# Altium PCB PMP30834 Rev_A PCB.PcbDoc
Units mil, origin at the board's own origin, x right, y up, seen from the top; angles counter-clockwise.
Board outline 2200 x 1400 mil, 4 copper layers (Top Layer, Signal Layer 1, Signal Layer 2, Bottom Layer), stack 61.668 mil thick; 56 components, 16 nets, 91 pads, 36 vias.
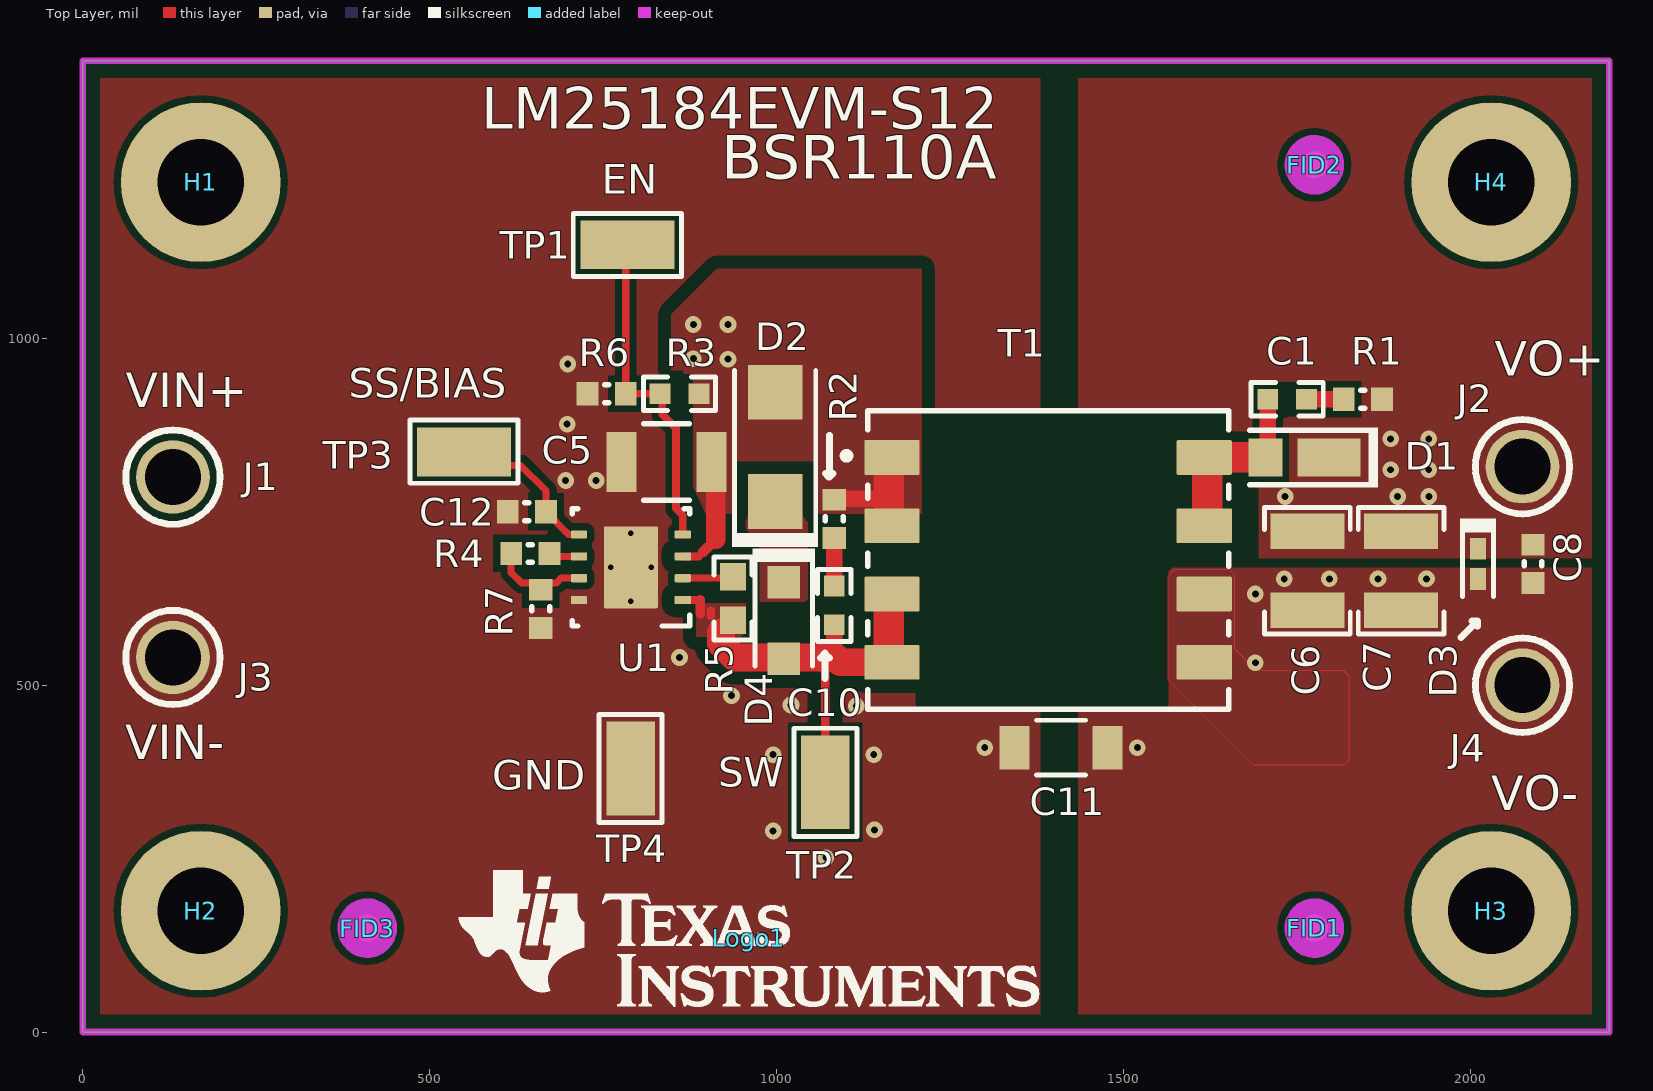
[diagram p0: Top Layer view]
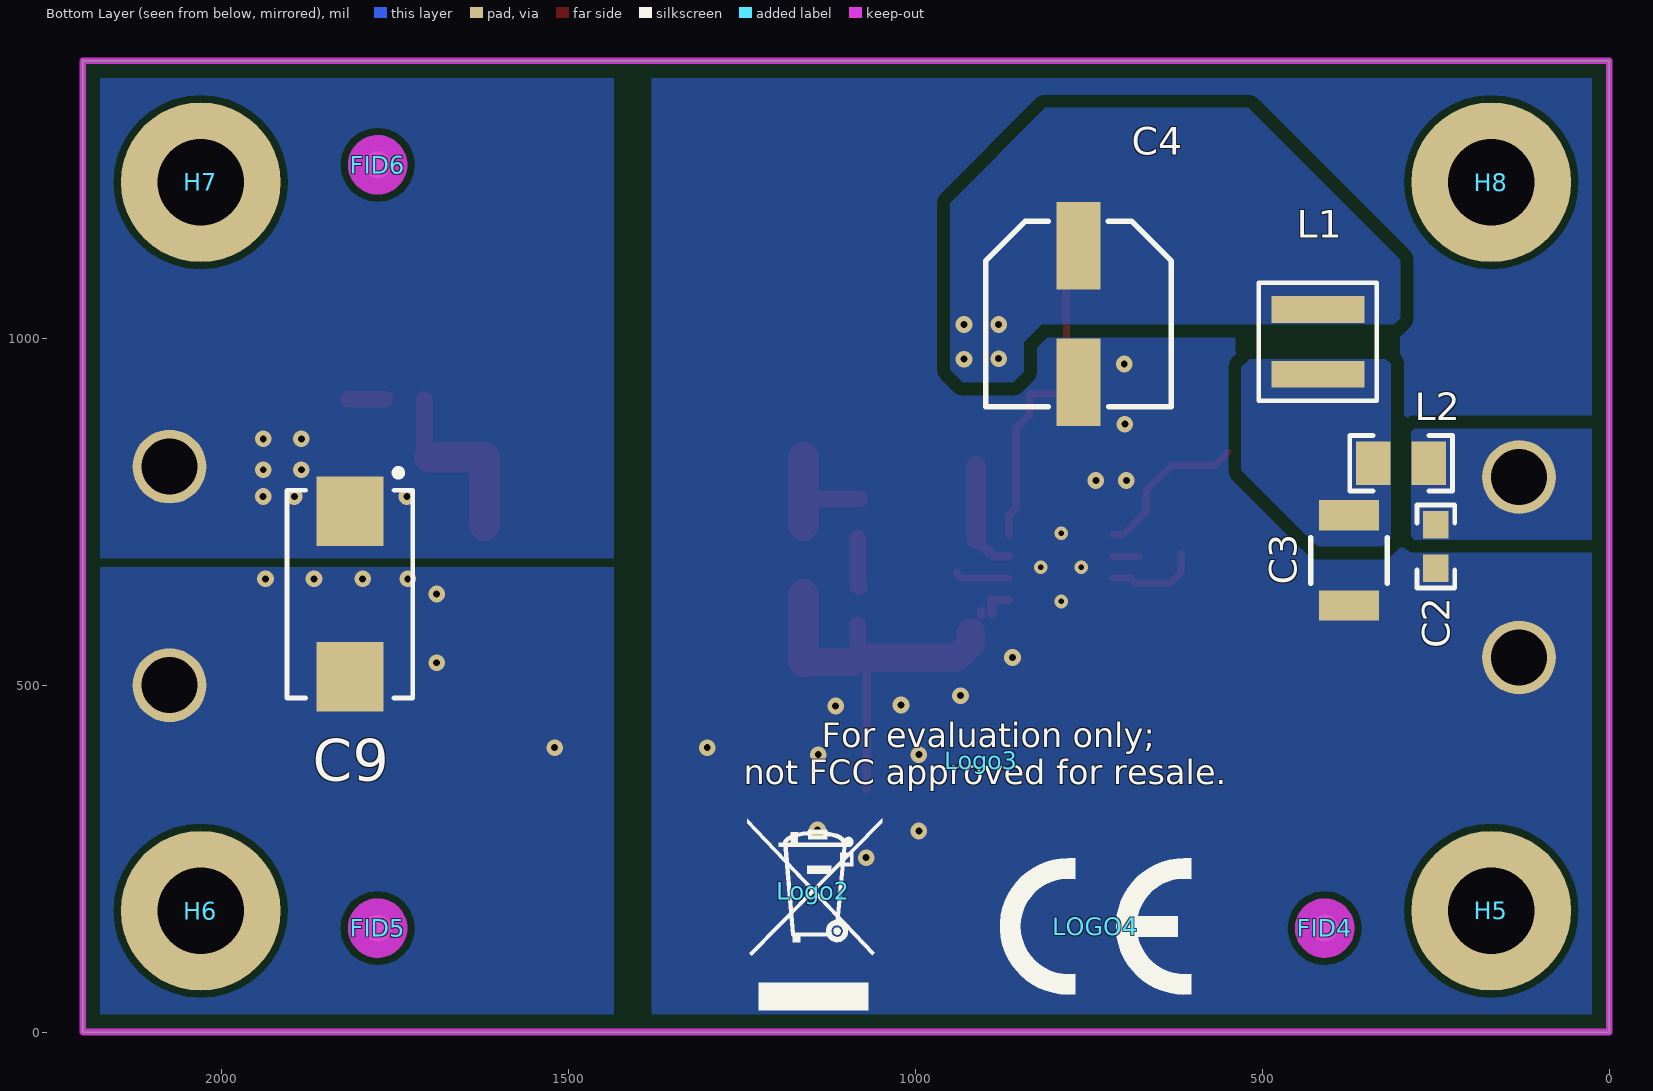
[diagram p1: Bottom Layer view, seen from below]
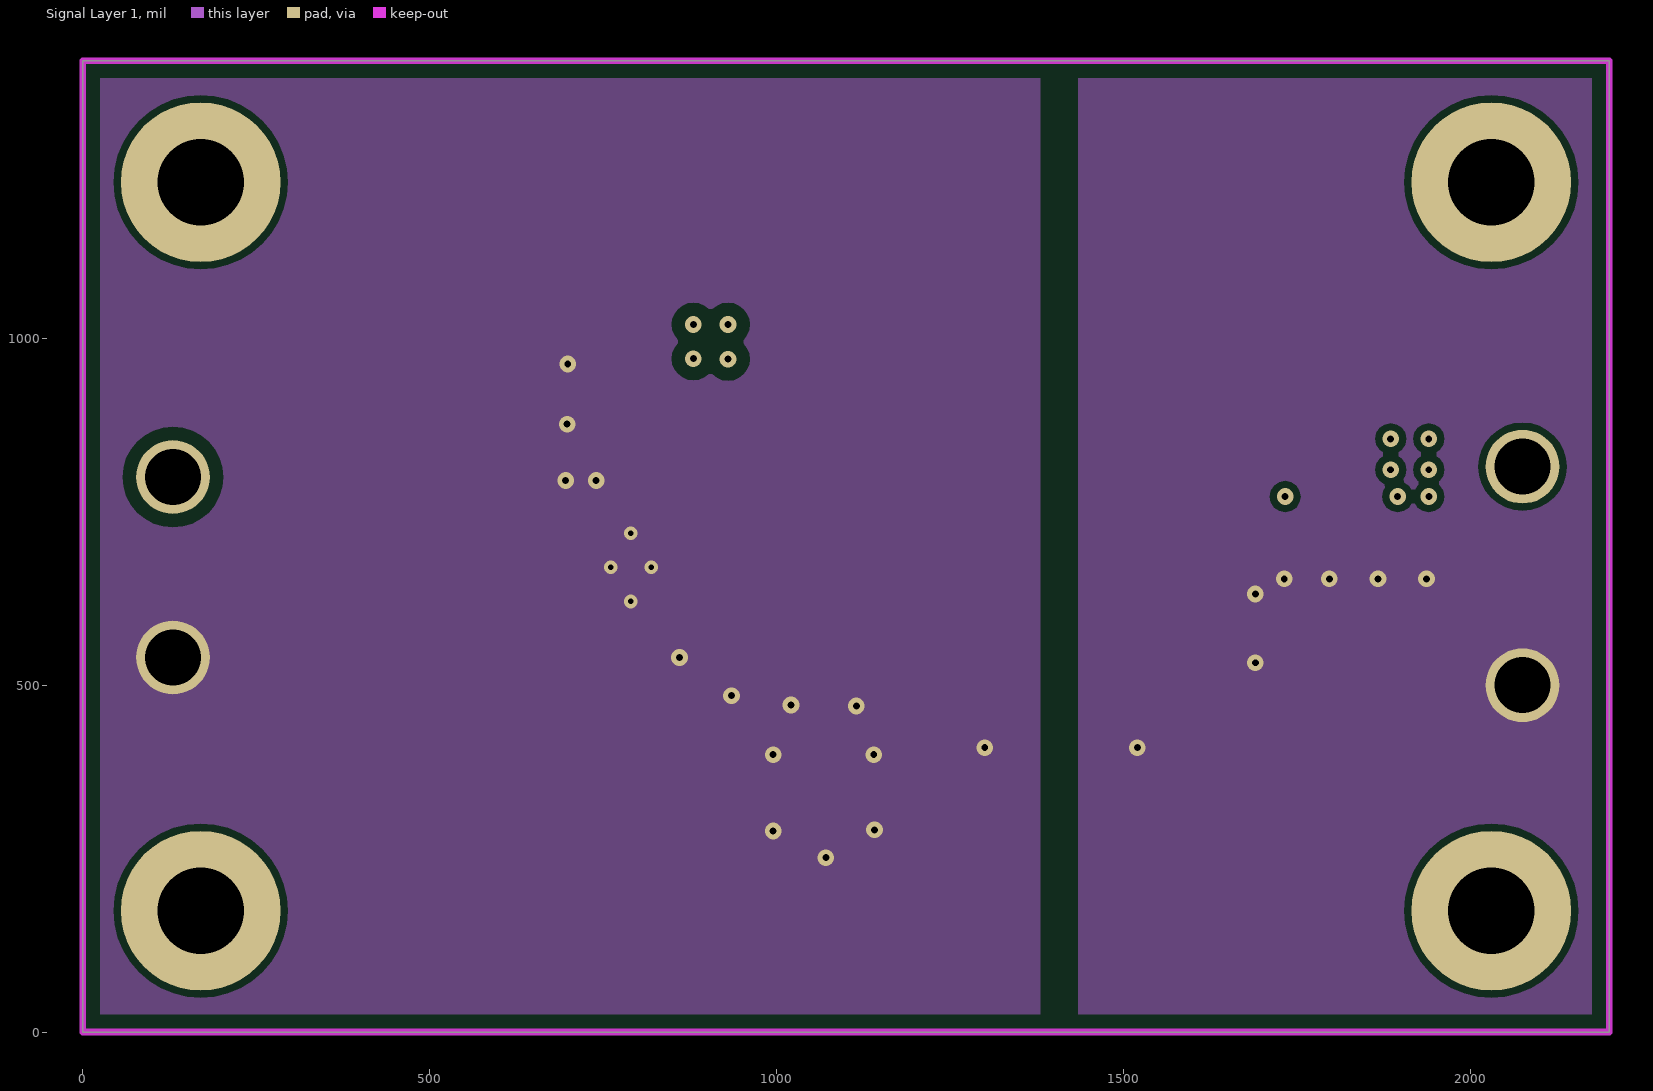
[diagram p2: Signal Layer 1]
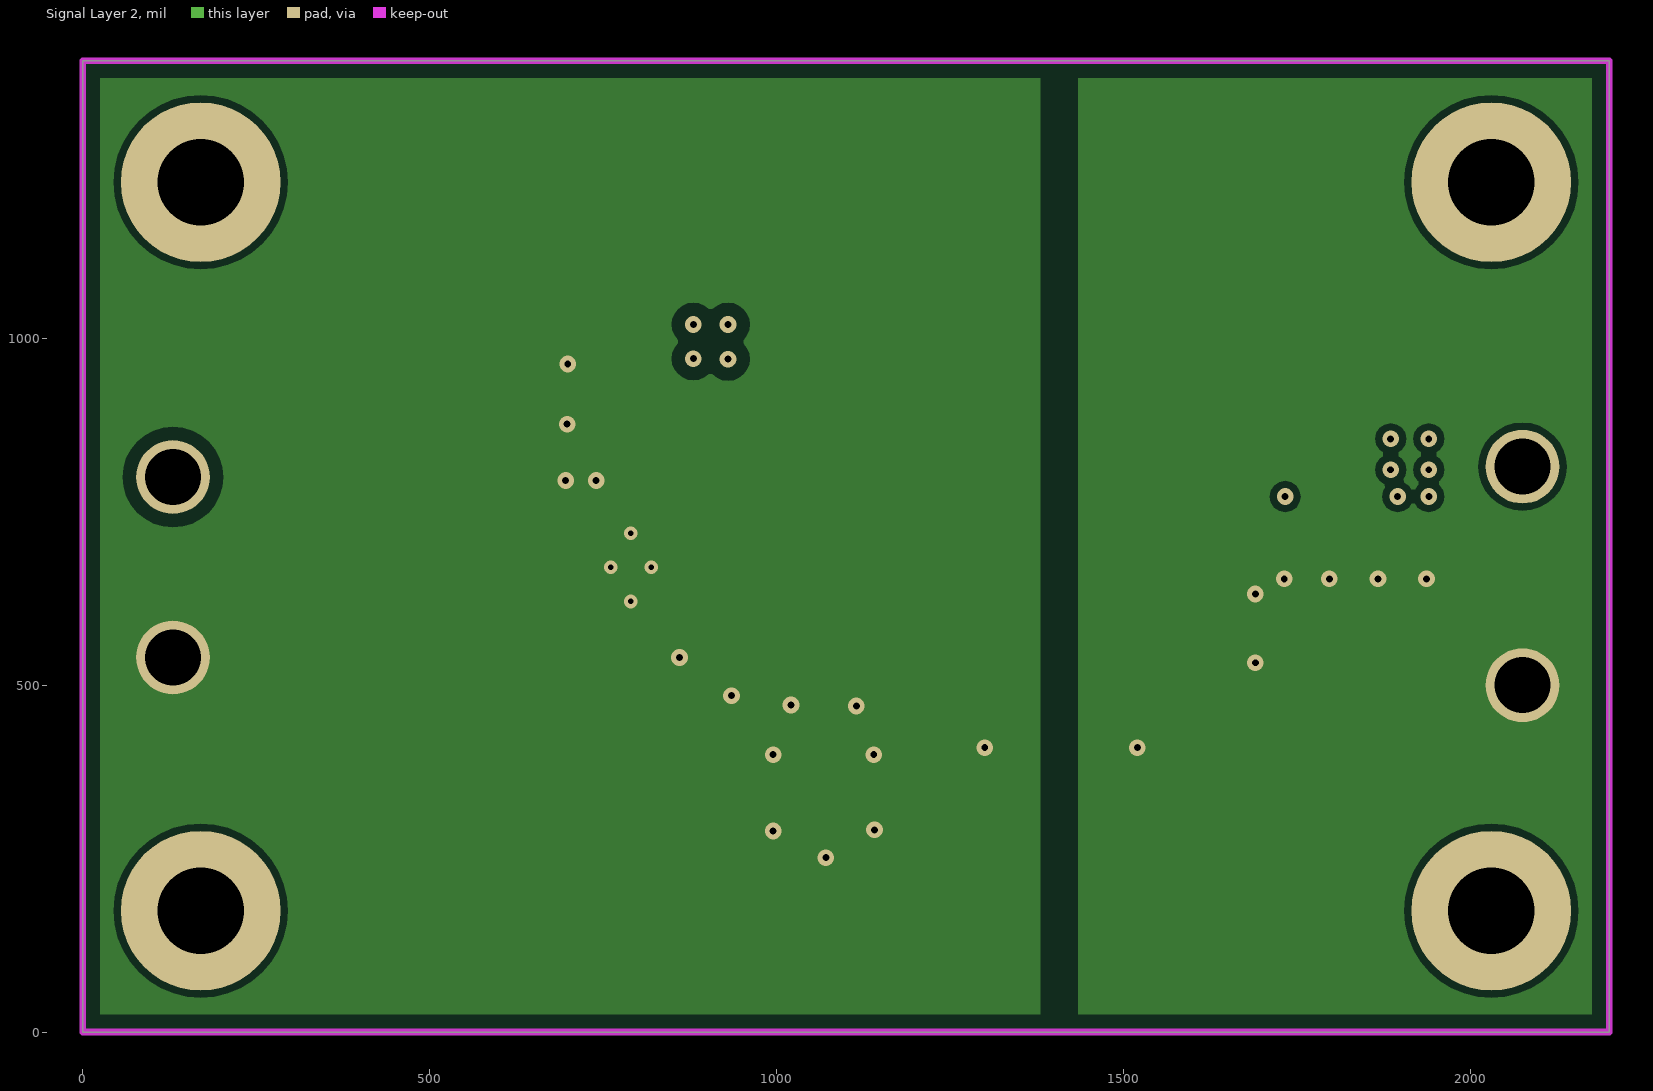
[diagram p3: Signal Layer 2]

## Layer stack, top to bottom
Top Solder: solder mask 0.4, Solder Resist, Dk 3.5
Top Layer: signal copper 1.417
Dielectric1: prepreg 6, FR-4 High Tg, Dk 4.2
Signal Layer 1: signal copper 1.417
Dielectric 2: core 44, FR-4 High Tg, Dk 4.2
Signal Layer 2: signal copper 1.417
Dielectric 3: dielectric 6, FR-4 High Tg, Dk 4.2
Bottom Layer: signal copper 1.417
Bottom Solder: solder mask 0.4, Solder Resist, Dk 3.5

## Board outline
0,0 0,1400 2200,1400 2200,0

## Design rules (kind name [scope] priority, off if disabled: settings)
AcuteAngle [All] p1: minimum=4.50000000000000E+0001 checktracksonly=FALSE
AssemblyTestPointUsage [All] p1: valid=2
BoardOutlineClearance BoardOutlineClearance_MountingHoles [OnCopper and InComponentClass('Mounting Holes')] p1: gap=40 ignorepadtopadclearanceinfootprint=FALSE
BoardOutlineClearance BoardOutlineClearance_Poly [OnCopper and IsPoly] p2: gap=25 ignorepadtopadclearanceinfootprint=FALSE
BoardOutlineClearance [OnCopper and Not InComponentClass('Logo') and not InComponentClass('FiducialMark') and not InRegion(1000,500,4000,800) and not InPoly] p3: gap=50 ignorepadtopadclearanceinfootprint=FALSE
Clearance Clearance_HV_Nets [InNetClass('HV_Nets')] p1: gap=19 ignorepadtopadclearanceinfootprint=FALSE
Clearance Clearance_Keepouts [((IsTrack Or IsArc) And Not InPoly) And IsFree and IsKeepOut vs ((IsTrack Or IsArc) And Not InPoly) And IsFree and IsKeepOut] p2: gap=0 ignorepadtopadclearanceinfootprint=FALSE
Clearance Clearance_Poly [InPolygon] p3: gap=10 ignorepadtopadclearanceinfootprint=FALSE
Clearance Clearance_FiducialMark [IsKeepOut and InComponentClass('FiducialMark') vs IsPad and InComponentClass('FiducialMark')] p4: gap=0 ignorepadtopadclearanceinfootprint=FALSE
Clearance [All] p5: gap=7.87 ignorepadtopadclearanceinfootprint=FALSE except(0: Arc-Hole Track-Hole SMDPad-Hole THPad-Hole Via-Hole Fill-Hole Poly-Hole Region-Hole Text-Hole)
ComponentClearance ComponentClearance_MountingHoles_FiducialMarks [InComponentClass('Mounting Holes') vs InComponentClass('FiducialMark')] p1: gap=50 collisioncheckmode=3 verticalgap=10 showdistances=FALSE
ComponentClearance ComponentClearance_Shunt [InComponentClass('Header') vs InComponentClass('Shunt')] p2: gap=0 collisioncheckmode=3 verticalgap=0 showdistances=FALSE
ComponentClearance ComponentClearance_Logo [InComponentClass('Logo')] p3: gap=50 collisioncheckmode=3 verticalgap=10 showdistances=FALSE
ComponentClearance ComponentClearance_ScrewToNut [(HasFootprint('NY PMS 440 0025 PH')) vs (HasFootprint('Keystone_1902C'))] p4: gap=5 collisioncheckmode=3 verticalgap=10 showdistances=FALSE
ComponentClearance ComponentClearance_MountingHoles [InComponentClass('Mounting Holes')] p5: gap=0 collisioncheckmode=3 verticalgap=0 showdistances=FALSE
ComponentClearance ComponentClearance_SmallPassives [HasFootprint('0201*') or HasFootprint('0402*') or HasFootprint('0508') or HasFootprint('0603*') or HasFootprint('0612') or HasFootprint('0805*') or HasFootprint('0815*') or HasFootprint('0830*') or HasFootprint('1206*') or HasFootprint('1210*') or HasFootprint('1808*') or HasFootprint('1812*') or HasFootprint('1825*') or HasFootprint('2010*') or HasFootprint('2220*') or HasFootprint('2225*') or HasFootprint('2512*') or HasFootprint('2728*') or HasFootprint('3518*') vs HasFootprint('0201*') or HasFootprint('0402*') or HasFootprint('0508') or HasFootprint('0603*') or HasFootprint('0612') or HasFootprint('0805*') or HasFootprint('0815*') or HasFootprint('0830*') or HasFootprint('1206*') or HasFootprint('1210*') or HasFootprint('1808*') or HasFootprint('1812*') or HasFootprint('1825*') or HasFootprint('2010*') or HasFootprint('2220*') or HasFootprint('2225*') or HasFootprint('2512*') or HasFootprint('2728*') or HasFootprint('3518*')] p6: gap=14.96 collisioncheckmode=3 verticalgap=10 showdistances=FALSE
ComponentClearance ComponentClearance_THtoSMT [IsThruComponent vs IsSMTComponent] p7: gap=20 collisioncheckmode=3 verticalgap=30 showdistances=FALSE
ComponentClearance ComponentClearance_THtoTH [IsThruComponent vs IsThruComponent] p8: gap=30 collisioncheckmode=3 verticalgap=30 showdistances=FALSE
ComponentClearance [All] p9: gap=10 collisioncheckmode=3 verticalgap=10 showdistances=FALSE
DiffPairsRouting [All] p1: maxlimit=100 minlimit=10 mostfreqgap=10 toplayer_minwidth=15 toplayer_maxwidth=15 toplayer_prefwidth=15 midlayer1_minwidth=15 midlayer1_maxwidth=15 midlayer1_prefwidth=15 midlayer2_minwidth=15 midlayer2_maxwidth=15 midlayer2_prefwidth=15 bottomlayer_minwidth=15 bottomlayer_maxwidth=15 bottomlayer_prefwidth=15 maxuncoupledlength=1000
FabricationTestPointUsage TestPointUsage [All] p1: valid=2 allowmultiple=FALSE
FabricationTestpoint Testpoint [All] p1: side=3 testpointundercomponent=TRUE minsize=40 maxsize=100 preferedsize=60 minholesize=0 maxholesize=40 preferedholesize=32 testpointgrid=1 allowsidetop=TRUE allowsidebottom=TRUE usegrid=TRUE gridtolerance=0.01
FanoutControl Fanout_LCC [IsLCC] p1: bgadir=Out bgaviamode=Centered fanoutstyle=Auto fanoutdirection=Alternating viagrid=1 // Fanout_LCC (Default Rule)
FanoutControl Fanout_BGA [IsBGA] p2: bgadir=Out bgaviamode=Centered fanoutstyle=Auto fanoutdirection=Alternating viagrid=1 // Fanout_BGA (Default Rule)
FanoutControl Fanout_Default [All] p4: bgadir=Out bgaviamode=Centered fanoutstyle=Auto fanoutdirection=Alternating viagrid=1 // Fanout_Default (Default Rule)
FanoutControl Fanout_Small [(CompPinCount < 5)] p5: bgadir=Out bgaviamode=Centered fanoutstyle=Auto fanoutdirection=OutThenIn viagrid=1 // Fanout_Small (Default Rule)
HoleSize [All] p1: absolutevalues=TRUE maxlimit=251 minlimit=7.87 maxpercent=80.000 minpercent=20.000
MinimumAnnularRing MinimumAnnularRing_ThermalPadVias [IsVia and InAnyComponent] p1: minimumring=5.91
MinimumAnnularRing [All] p2: minimumring=7
MinimumSolderMaskSliver MinimumSolderMaskSliver_Logo [InComponentClass('Logo') vs InComponentClass('Logo')] p1: minsoldermaskwidth=0.7
MinimumSolderMaskSliver [All] p2: minsoldermaskwidth=3.94
PlaneConnect [All] p1: planeconnectstyle=Relief reliefexpansion=10 reliefentries=4 reliefconductorwidth=10 reliefairgap=10
PolygonConnect [All] p1: connectstyle=Direct reliefconductorwidth=10 reliefentries=4 polygonreliefangle="90 Angle" airgapwidth=10
RoutingVias ThermalPadVias [IsVia and InAnyComponent] p1: holewidth=7.87 width=19.68 viastyle="Through Hole" minholewidth=7.87 minwidth=19.68 maxholewidth=12.99 maxwidth=23.62
RoutingVias [All] p2: holewidth=16 width=34 viastyle="Through Hole" minholewidth=7.87 minwidth=12 maxholewidth=40 maxwidth=65
SilkToBoardRegionClearance [Not ((IsComment or IsDesignator) And (Hide <> 'False')) and not InRegion(1000,500,4000,800)] p1:
SilkToSilkClearance SilkToSilkClearance_Pb-FreeLogo [(HasFootprint('Pb-Free_Overlay_Medium') OR HasFootprint('Pb-Free_Overlay_Small')) vs (HasFootprint('Pb-Free_Overlay_Medium') OR HasFootprint('Pb-Free_Overlay_Small'))] p1: silktosilkclearance=0
SilkToSilkClearance [All] p2: silktosilkclearance=4
SilkToSolderMaskClearance [IsPad] p1: minsilkscreentomaskgap=5 clearancetoexposedcopper=TRUE
SilkToSolderMaskClearance "Silk to Solder Mask Opening" [All] p2: minsilkscreentomaskgap=4 clearancetoexposedcopper=FALSE
SolderMaskExpansion [All] p1: expansion=1.97
Width [All] p1: maxlimit=100 minlimit=6 preferedwidth=10 checkconnectedcopper=TRUE
15 further rules are at their usual default settings.

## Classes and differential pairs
component class "Mounting Holes": H1 H2 H3 H4 H5 H6 H7 H8
net class HV_Nets: NetC2_1 NetC3_2 NetC4_1 NetC10_2
component class AssemblyNote: ZZ2 ZZ3 ZZ4
component class FiducialMark: FID1 FID2 FID3 FID4 FID5 FID6
component class BSR110A-HW: FID1 FID2 FID3 FID4 FID5 FID6 H1 H2 H3 H4 H5 H6 H7 H8 Logo1 Logo2 Logo3 LOGO4 ZZ2 ZZ3 ZZ4
component class Logo: Logo1
component class BSR110A-SCH: C1 C2 C3 C4 C5 C6 C7 C8 C9 C10 C11 C12 D1 D2 D3 D4 D? J1 J2 J3 J4 L1 L2 R1 R2 R3 R4 R5 R6 R7 SS/Bias T1 TP1 TP2 TP3 TP4 U1

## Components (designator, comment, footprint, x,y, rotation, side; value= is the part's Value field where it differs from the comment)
C1 "GRM1885C2A220JA01D" 0603_HV 1735.87,912.2 r180 top value=22pF
C2 "C0603C104K5RACAUTO" 0603 250,700 r270 bottom value=0.1uF
C3 "CGA6P3X7S1H106K250AB" 1210_280 375,680 r90 bottom value=10uF
C4 "EEH-ZC1H220P" Panasonic_D 765,1035 r270 bottom value=22uF
C5 "CGA6P3X7S1H106K250AB" 1210_280 841.14,821.58 r0 top value=10uF
C6 "TMK325B7226KMHP" 1210_270 1765,665 r270 top value=22uF
C7 "TMK325B7226KMHP" 1210_270 1900,665 r270 top value=22uF
C8 "C0603C104K5RACAUTO" 0603L 2090,675 r270 top value=0.1uF
C9 "T598D107M016ATE050" 7343-31 1815,631.45 r270 bottom value=100uF
C10 "GRM1885C2A220JA01D" 0603_HV 1083,615.04 r270 top value=22pF
C11 "202R18W102KV4E" 1206_190 1410,410 r180 top value=1000pF
C12 "GCM188R71E473KA37D" 0603L 640,750 r180 top value=0.047uF
D1 "FSV360FP" SOD-123HE 1760.68,828.3 r180 top value=60V
D2 "3SMAJ5932B-TP" SMA 997.8,843.54 r90 top value=20V
D3 "BZT52C13T-7" SOD-523 2010.79,675 r270 top value=13V
D4 "PMEG60T30ELRX" SOD-123W 1010.16,593.35 r270 top value=60V
FID1 "Fiducial" Fiducial10-20 1775,150 r270 top
FID2 "Fiducial" Fiducial10-20 1775,1250 r270 top
FID3 "Fiducial" Fiducial10-20 410,150 r270 top
FID4 "Fiducial" Fiducial10-20 410,150 r180 bottom
FID5 "Fiducial" Fiducial10-20 1775,150 r180 bottom
FID6 "Fiducial" Fiducial10-20 1775,1250 r180 bottom
H1 "PMSSS 440 0025 PH" B_F_PMSSS4400025PH 170,1225 r0 top
H2 "PMSSS 440 0025 PH" B_F_PMSSS4400025PH 170,175 r0 top
H3 "PMSSS 440 0025 PH" B_F_PMSSS4400025PH 2030,175 r0 top
H4 "PMSSS 440 0025 PH" B_F_PMSSS4400025PH 2030,1225 r0 top
H5 "1902C" Keystone_1902C 170,175 r180 bottom
H6 "1902C" Keystone_1902C 2030,175 r180 bottom
H7 "1902C" Keystone_1902C 2030,1225 r180 bottom
H8 "1902C" Keystone_1902C 170,1225 r180 bottom
J1 "1573-2" Keystone1573-2 130,800 r270 top
J2 "1573-2" Keystone1573-2 2075,815 r0 top
J3 "1573-2" Keystone1573-2 130,540 r0 top
J4 "1573-2" Keystone1573-2 2075,500 r0 top
L1 "XFL4030-472MEB" XFL4030 420,995 r90 bottom value=4.7uH
L2 "742792021" 0805_HV 300,820 r0 bottom value="22 ohm"
Logo1 "Texas Instruments" TI_Stacked_Overlay_Small 960,135 r0 top
Logo2 "WEEE logo" WEEE_Minimum 1147,204 r180 bottom
Logo3 "FCC disclaimer" FCC_disclaimer_stacked 905,392 r180 bottom
LOGO4 "CE Mark" CE_Mark_5mm 740.25,152.45 r180 bottom
R1 "CRCW0603100RFKEA" 0603L 1845,912.2 r180 top value=100
R2 "CRCW0603100RFKEA" 0603L 1083,739.72 r90 top value=100
R3 "CRCW0603261KFKEA" 0603_HV 860,920 r0 top value=261k
R4 "CRCW0603261KFKEA" 0603L 645,690 r0 top value=261k
R5 "CRCW0603124KFKEA" 0603 937.1,625 r270 top value=124k
R6 "CRCW060397K6FKEA" 0603L 755,920 r0 top value=97.6k
R7 "CRCW060312K1FKEA" 0603L 660,610 r90 top value=12.1k
T1 "ZA9672-BE" FP-ZA9672-BE_SMD8-MFG 1391.27,680.67 r0 top
TP1 "EN" Testpoint_Keystone_Miniature 785,1135 r0 top
TP2 "SW" Testpoint_Keystone_Miniature 1070,360 r90 top
TP3 "SS/BIAS" Testpoint_Keystone_Miniature 549.37,836.18 r180 top
TP4 "GND" Testpoint_Keystone_Miniature 790,380 r270 top
U1 "LM25184QNGURQ1" NGU0008C 790,670 r180 top
ZZ2 "These assemblies must be clean and free from flux and all contaminants.  Use of no clean flux is not acceptable." AssemblyNote 165,1985.56 r0 top
ZZ3 "These assemblies must comply with workmanship standards IPC-A-610 Class 2., unless otherwise specified." AssemblyNote 165,1897 r0 top
ZZ4 "Mounting hardware H1 thru H8 to be installed in corner holes provided.  Screw inserted from component side, standoff on solder side." AssemblyNote 164,1797 r0 top

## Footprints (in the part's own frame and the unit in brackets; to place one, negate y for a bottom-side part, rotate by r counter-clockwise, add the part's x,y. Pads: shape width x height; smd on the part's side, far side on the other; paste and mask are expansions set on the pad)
0603 [mm] "0603 from SM-752 data"
  rect 1x0.95 smd: 1(-0.8,0) 2(0.8,0)
  silkscreen extent -1.52,-0.69 1.52,0.69, body extent -0.87,-0.47 0.87,0.47, height 1
0603_HV [mil] "Ernesto recommended land pattern.  26 mil between pads."
  rect 30x30 smd: 1(-28,0) 2(28,0)
  silkscreen extent -52,-24 52,24, body extent -34,-19 34,19, height 39
0603L [mm] "0603 from SM-752 data"
  rect 0.8x0.85 smd: 1(-0.7,0) 2(0.7,0)
  silkscreen extent -0.07,-0.33 0.07,0.33, body extent -0.87,-0.47 0.87,0.47, height 1
0805_HV [mil] "0805 with 30mil clearance between pads"
  rect 50x63 smd: 1(-40,0) 2(40,0)
  silkscreen extent -74,-40 74,40, body extent -43,-29 43,29, height 57
1206_190 [mm] "1206_190"
  rect 1.1x1.6 smd: 1(-1.7,0) 2(1.7,0)
  silkscreen extent -0.9,-1 0.9,1, body extent -1.75,-0.95 1.75,0.95, height 1.9
1210_270 [mm] "1210"
  rect 1.3x2.7 smd: 1(-1.45,0) 2(1.45,0)
  silkscreen extent -2.32,-1.57 2.32,1.57, body extent -1.7,-1.35 1.7,1.35, height 2.7
1210_280 [mm] "SMD, 2-Leads, Body 3.6x2.8mm, Height 2.8mm"
  rect 1.1x2.2 smd: 1(-1.65,0) 2(1.65,0)
  silkscreen extent -0.84,-1.4 0.84,1.4, body extent -1.8,-1.4 1.8,1.4, height 2.8
7343-31 [mm] "Medium Density based on Kemet T495 dimensions"
  rect 2.55x2.45 smd: 1(-3.025,0) 2(3.025,0)
  silkscreen extent -4.56,-2.3 3.8,2.3, body extent -3.8,-2.3 3.8,2.3, height 3.1
AssemblyNote [mil] "Assembly Note"
B_F_PMSSS4400025PH [mil] "MACHINE SCREW PAN PHILLIPS 4-40"
  round 230 hole 125: 1(0,0)
  body extent -109,-109 110,110, height 79
CE_Mark_5mm [mil] "Minimum text height for CE Mark"
  silkscreen extent -138,-98 138,98
FCC_disclaimer_stacked [mil]
Fiducial10-20 [mm]
  round 1 smd mask+0.5: 1(0,0)
  Top Layer keep-out circle w1.178: c0,0 r0.5
FP-ZA9672-BE_SMD8-MFG [mm]
  rrect8% 2.03x1.27 smd paste+0 mask+0: 1(-5.715,3.75) 2(-5.715,1.25) 3(-5.715,-1.25) 4(-5.715,-3.75) 5(5.715,-3.75) 6(5.715,-1.25) 7(5.715,1.25) 8(5.715,3.75)
  silkscreen extent -7.5,-5.46 6.61,5.46, body extent -6.83,-5.56 6.83,5.56, height 0.25
Keystone1573-2 [mm] "Double Turret"
  round 2.7 hole 2.05: 1(0,0)
  silkscreen extent -1.73,-1.73 1.73,1.73, body extent -1.18,-1.18 1.17,1.18, height 4.72
Keystone_1902C [mil] "Hex Standoff, 4-40 threaded, nylon"
  round 1 on Mech4: 0(0,0)
  body extent -145,-126 146,126, height 501
NGU0008C [mm] "SON, 8-Leads, Body 4x4mm, Pitch 0.8mm"
  rrect33% 0.6x0.3 smd: 1(-1.9,1.2) 2(-1.9,0.4) 3(-1.9,-0.4) 4(-1.9,-1.2) 5(1.9,-1.2) 6(1.9,-0.4) 7(1.9,0.4) 8(1.9,1.2)
  rrect8% 1.75x1.31 on Top Paste: 9(0,0.755) 9(0,-0.755)
  rrect5% 1.98x3 smd paste-1.5: 9(0,0)
  silkscreen extent -2.15,-2.15 2.15,2.15, body extent -2,-2 2,2, height 0.77
Panasonic_D [mm] "SMD, 2-Leads, Dia 6.3mm"
  rect 3.2x1.6 smd: 1(-2.5,0) 2(2.5,0)
  silkscreen extent -3.4,-3.4 3.4,3.4, body extent -3.4,-3.4 3.4,3.4, height 6.11
SMA [mm] "Molded Diode, 2-Leads, Body 4.3x2.6mm, IPC Medium Density, based on OnSemi component dimensions and land pattern"
  rect 2x2 smd: 1(-2,0) 2(2,0)
  silkscreen extent -3.66,-1.57 2.79,1.57, body extent -2.6,-1.3 2.6,1.3, height 2.42
SOD-123HE [mm] "SMD, 2-Leads, Body 2.8x1.8mm"
  rect 2.3x1.4 smd: 1(-0.9,0)
  rect 1.25x1.4 smd: 2(1.425,0)
  silkscreen extent -2.7,-1.1 2,1.1, body extent -1.5,-0.97 1.5,0.97, height 1
SOD-123W [mm] "NXP recommended land pattern"
  rect 1.2x1.2 smd paste-0.05: 1(-1.4,0) 2(1.4,0)
  silkscreen extent -2.64,-1.14 1.68,1.14, body extent -1.85,-0.95 1.85,0.95, height 1.1
SOD-523 [mm] "NXP Semiconductor recommended land pattern, nominal STEP model"
  rect 0.8x0.6 smd paste-0.05: 1(-0.55,0) 2(0.55,0)
  silkscreen extent -1.65,-0.66 1.2,0.66, body extent -0.8,-0.4 0.8,0.4, height 0.72
Testpoint_Keystone_Miniature [mil] "Miniature SMT test point"
  rect 135x70 smd: 1(0,0)
  silkscreen extent -78,-46 78,45, body extent -52,-20 52,20, height 61
TI_Stacked_Overlay_Small [mil]
  silkscreen extent -418,-98 418,98
WEEE_Minimum [mil] "WEEElie bin"
  silkscreen extent -95,-172 99,104
XFL4030 [mm] "Coilcraft XFL4030"
  rect 0.98x3.4 smd: 1(-1.185,0) 2(1.185,0)
  silkscreen extent -2.16,-2.16 2.16,2.16, body extent -2.15,-2.15 2.15,2.15, height 3.1

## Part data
C1 C10: library part CMP-0007255-4, "CAP, CERM, 22 pF, 100 V, +/- 5%, C0G/NP0, 0603", Cap_Case=0603, Manufacturer=MuRata, Supplier Part Number 1=490-1335-1-ND, TempCo=C0G/NP0, Tolerance_%=5%, Value1=Unknown, Value2=100V, ValueDisplayed=22pF
C2 C8: library part CMP-0079602-1, "CAP, CERM, 0.1 µF, 50 V,+/- 10%, X7R, AEC-Q200 Grade 1, 0603", Cap_Case=0603, Manufacturer=Kemet, Supplier Part Number 1=399-6856-1-ND, TempCo=X7R, Tolerance_%=10%, Value2=50V, ValueDisplayed=0.1µF
C3 C5: library part CMP-0009164-2, "CAP, CERM, 10 uF, 50 V, +/- 10%, X7S, AEC-Q200 Grade 1, 1210", Cap_Case=1210_280, Manufacturer=TDK, Supplier Part Number 1=445-7004-1-ND, TempCo=X7S, Tolerance_%=10%, Value1="0.002827 ohm", Value2=50V, ValueDisplayed=10uF
C4: library part CMP-0012597-3, "CAP, Polymer Hybrid, 22 uF, 50 V, +/- 20%, 0.08 ohm, AEC-Q200 Grade 1, D6.3xL5.8mm SMD", Cap_Case=6.3x5.8, Manufacturer=Panasonic, Supplier Part Number 1=P15463CT-ND, Tolerance_%=20%, Value1="0.08 ohm", Value2=50V, ValueDisplayed=22uF
C6 C7: library part CMP-0080552-1, "CAP, CERM, 22 µF, 25 V,+/- 10%, X7R, AEC-Q200 Grade 1, 1210", Cap_Case=1210, Manufacturer="Taiyo Yuden", Supplier Part Number 1=587-5949-1-ND, TempCo=X7R, Tolerance_%=10%, Value2=25V, ValueDisplayed=22µF
C9: library part CMP-0012660-3, "CAP, Tantalum Polymer, 100 uF, 16 V, +/- 20%, 0.05 ohm, AEC-Q200 Grade 1, 7343-31 SMD", Cap_Case=7343-31, Manufacturer=Kemet, Supplier Part Number 1=399-12105-1-ND, Tolerance_%=20%, Value1="0.05 ohm", Value2=16V, ValueDisplayed=100uF
C11: library part CMP-0008572-2, "CAP, CERM, 1000 pF, 2000 V, +/- 10%, X7R, 1206_190", Cap_Case=1206, Manufacturer="Johanson Technology", TempCo=X7R, Tolerance_%=10%, Value1=Unknown, Value2=2000V, ValueDisplayed=1000pF
C12: library part CMP-0007141-3, "CAP, CERM, 0.047 uF, 25 V, +/- 10%, X7R, AEC-Q200 Grade 1, 0603", Cap_Case=0603, Manufacturer=MuRata, Supplier Part Number 1=490-8018-1-ND, TempCo=X7R, Tolerance_%=10%, Value1=Unknown, Value2=25V, ValueDisplayed=0.047uF
D1: library part CMP-0028825-2, "Diode, Schottky, 60 V, 3 A, AEC-Q101, SOD-123HE", Manufacturer="Fairchild Semiconductor", Value1=3A, Value2=0.65V
D2: library part CMP-0005511-4, "Diode, Zener, 20 V, 3 W, SMA", Manufacturer="Micro Commercial Components", Power_W=3W
D3: library part CMP-0005879-5, "Diode, Zener, 13 V, 300 mW, SOD-523", Manufacturer="Diodes Inc.", Power_W=300mW, Value1=0.3W
D4: library part CMP-0085903-1, "Diode, Schottky, 60 V, 3 A, AEC-Q101, SOD-123W", Manufacturer=Nexperia, Value1=3A, Value2=0.62V
FID1 FID2 FID3 FID4 FID5 FID6: library part CMP-0077181-1, "Fiducial mark.  There is nothing to buy or mount.", Manufacturer=N/A
H1 H2 H3 H4: library part CMP-0003715-1, "MACHINE SCREW PAN PHILLIPS 4-40", Manufacturer="B&F Fastener Supply", Supplier Part Number 1=H703-ND
H5 H6 H7 H8: library part CMP-0003610-1, "Standoff, Hex, 0.5\"L #4-40 Nylon", Manufacturer=Keystone, Supplier Part Number 1=36-1902C-ND
J1 J2 J3 J4: library part CMP-0055119-1, "Terminal, Turret, TH, Double", Manufacturer=Keystone, Supplier Part Number 1=36-1573-2-ND
L1: library part CMP-0061153-1, "Inductor, Shielded, Composite, 4.7 uH, 2.1 A, 0.03 ohm, SMD", Manufacturer=Coilcraft, Value1="0.03 ohm", Value2=2.1A, ValueDisplayed=4.7uH
L2: library part CMP-0003072-1, "Ferrite Bead, 22 ohm @ 100 MHz, 6 A, 0805", Manufacturer="Wurth Elektronik", Supplier Part Number 1=732-4637-1-ND, Value1="0.008 ohm", Value2=6A, ValueDisplayed="22 ohm"
Logo1: library part CMP-0074838-1, "Texas Instrument Corporate Signature"
Logo2: library part CMP-0074769-1
Logo3: library part CMP-0074847-1, "FCC_disclaimer"
LOGO4: library part CMP-0074844-1
R1 R2: library part CMP-0021991-4, "RES, 100, 1%, 0.1 W, AEC-Q200 Grade 0, 0603", Manufacturer=Vishay-Dale, Power_W=100mW, Supplier Part Number 1=541-100HCT-ND, TempCo="100 ppm/C", Tolerance_%=1%, Value2=0.1W, Value_Code=100R, ValueDisplayed=100
R3 R4: library part CMP-0022244-4, "RES, 261 k, 1%, 0.1 W, AEC-Q200 Grade 0, 0603", Manufacturer=Vishay-Dale, Power_W=100mW, Supplier Part Number 1=541-261KHCT-ND, TempCo="100 ppm/C", Tolerance_%=1%, Value2=0.1W, Value_Code=261k
R5: library part CMP-0022026-4, "RES, 124 k, 1%, 0.1 W, AEC-Q200 Grade 0, 0603", Manufacturer=Vishay-Dale, Power_W=100mW, Supplier Part Number 1=541-124KHCT-ND, TempCo="100 ppm/C", Tolerance_%=1%, Value2=0.1W, Value_Code=124k
R6: library part CMP-0022663-4, "RES, 97.6 k, 1%, 0.1 W, AEC-Q200 Grade 0, 0603", Manufacturer=Vishay-Dale, Power_W=100mW, Supplier Part Number 1=541-97.6KHCT-ND, TempCo="100 ppm/C", Tolerance_%=1%, Value2=0.1W, Value_Code=97k6, ValueDisplayed=97.6k
R7: library part CMP-0022030-4, "RES, 12.1 k, 1%, 0.1 W, AEC-Q200 Grade 0, 0603", Manufacturer=Vishay-Dale, Power_W=100mW, Supplier Part Number 1=541-12.1KHCT-ND, TempCo="100 ppm/C", Tolerance_%=1%, Value2=0.1W, Value_Code=12k1, ValueDisplayed=12.1k
T1: library part CMP-0088070-1, "FLYBACK TRANSFORMER", Manufacturer=Coilcraft
TP1 TP2 TP3 TP4: library part CMP-0055152-1, "Test Point, Miniature, SMT", Manufacturer=Keystone, PartNumber=5015, Supplier Part Number 1=36-5015TR-ND
U1: library part CMP-0860959-2, "42-VIN PSR Flyback DC/DC Converter with 65-V, 4-A Integrated MOSFET, NGU0008C (WSON-8)", Alternate Manufacturer="Texas Instruments"
ZZ2 ZZ3 ZZ4: library part AssemblyNote

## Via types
v1: diameter 24, hole 10, Top Layer to Bottom Layer, tented both sides, 32 vias
v2: diameter 19.68, hole 7.87, Top Layer to Bottom Layer, 4 vias

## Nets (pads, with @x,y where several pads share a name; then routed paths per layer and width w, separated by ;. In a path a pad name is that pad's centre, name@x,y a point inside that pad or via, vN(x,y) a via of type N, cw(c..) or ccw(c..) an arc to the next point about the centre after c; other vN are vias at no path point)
NetC1_1: C1.1 R1.2 | length 53.6
  Top Layer w24: C1.1 R1.2
NetC1_2: C1.2 D1.2 T1.7 T1.8 | length 272.2
  Top Layer w24: D1.2@1705.56,828.3 1707.87,830.61 C1.2
  Top Layer w32: T1.7@1620.8,729.88 T1.7@1627.27,736.35
  Top Layer w44: T1.7@1620.8,729.88 1620.8,828.3 D1.2@1700.58,828.3
NetC2_1: C2.1 J1.1 L2.1
NetC3_2: C3.2 L1.1 L2.2
NetC4_1: C4.1 C5.2 D2.2 L1.2 R2.2 R3.2 T1.1 T1.2 U1.3 | length 344.1
  Top Layer w11: 887.88,685.75 894.25,692.12
  Top Layer w11.8: U1.3 887.88,685.75
  Top Layer w15: 894.25,692.12 912.13,710
  Top Layer w24: R2.2@1081,768.56 1159.63,768.56 1161.74,770.67
  Top Layer w28: 912.13,710 C5.2@912.13,816.73
  Top Layer w44: T1.2@1161.74,729.88 1161.74,770.67 T1.1@1161.74,828.3
  other v1: 930,970 880.03,970.68 880,1020 930,1020
NetC6_1: C6.1 C7.1 C8.1 C9.1 D1.1 D3.1 J2.1 R1.1
  other v1: 1732.87,772 1895,772 1940,772 1885,810.59 1939.92,810.59 1885,855 1939.92,855
NetC10_1: C10.1 R2.1 | length 70.5
  Top Layer w24: C10.1@1080,643 C10.1@1081,644 ; C10.1 R2.1
NetC10_2: C10.2 D4.2 R5.2 T1.3 T1.4 TP2.1 U1.1 | length 663.1
  Top Layer w11.8: U1.1 890,622.75 ; 905,600 905,607.75
  Top Layer w12: TP2.1@1070,350 TP2.1 1070,525 1085,540
  Top Layer w14: 890,603.35 890,622.75
  Top Layer w24: C10.2 1083,542 1085,540
  Top Layer w40: R5.2@919.76,576.16 919.76,560.24 940,540 1085,540 1092,533 T1.4@1160,533
  Top Layer w44: T1.4@1160,533 1161.74,534.74 T1.3@1161.74,631.45
NetC12_1: C12.1 TP3.1 U1.5 | length 232.9
  Top Layer w10: TP3.1 568.56,817 631,817 667.56,780.44 C12.1 700.32,717.24 U1.5
NetD2_1: D2.1 D4.1
NetR3_1: R3.1 R6.2 TP1.1 U1.4 | length 479.6
  Top Layer w11: R6.2 TP1.1@782.56,1132.56 ; R6.2@783.05,920 797.56,920 835,920 835,890.27 855,870.27 855,755 864.8,745.2 U1.4
NetR4_1: R4.1 R7.2 U1.7 | length 134.2
  Top Layer w10: R4.1@617.56,690 R4.1 617.44,662.76 632.64,647.56 660,647.56 682.56,647.56 689.25,654.25 U1.7
NetR4_2: R4.2 U1.6 | length 38.4
  Top Layer w10: R4.2@676.81,685.75 U1.6
NetR5_1: R5.1 U1.2 | length 80.9
  Top Layer w10: U1.2 934.83,654.25 940,659.42 R5.1@940,663
PGND: C2.2 C3.1 C4.2 C5.1 C11.2 C12.2 J3.1 R6.1 R7.1 TP4.1 U1.8 U1.9@790,670
  other v1: 1071.04,251.5 995,290 1141.04,291.5 995,400 1140,400 1300,410 1115,470 1020.7,471.45 935,485 860,540 696,795 740,795 698.14,876.2 699,963
  other v2: 790,620.79 760.86,670 819.13,670 790,719.21
SGND: C6.2 C7.2 C8.2 C9.2 C11.1 D3.2 J4.1 T1.5 T1.6
  other v1: 1520,410 1690,532.42 1690,631.45 1731.65,653.35 1796.65,653.35 1866.65,653.35 1936.65,653.35
pads on no net: FID1.1 FID2.1 FID3.1 FID4.1 FID5.1 FID6.1 H1.1 H2.1 H3.1 H4.1 H5.0 H6.0 H7.0 H8.0 U1.9@790,640.27 U1.9@790,699.72

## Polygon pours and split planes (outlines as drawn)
NetC6_1 on Top Layer "TOP_LAYER_NETC6_1_P239" (solid, remove dead copper, pour order 239): 2200,682.79 1653.98,682.79 1653.98,893.35 1435,893.35 1435.01,1400 2200,1400 2200,1020 2200,834.45
NetD2_1 on Top Layer "Top Layer-No Net 5" (solid, pour order 236): 1045,816.73 1045,620 975.5,620 975.47,705.68 955.64,725.52 955.64,816.73
NetC4_1 on Top Layer "Top Layer-No Net 4" (solid, pour order 235): 848.41,948.73 848.41,1034.66 913.74,1100 1209.36,1100 1209.36,747.4 1059.63,747.4 898.21,747.4 879.5,786.96 879.5,948.73
PGND on Top Layer "Top Layer-No Net" (solid, pour order 241): 0,1400 1060,1400 1380,1400 1380,898.33 1200,898.33 1200,465 1380,465 1380,0 0,0
SGND on Top Layer "Top Layer-No Net 1" (solid, pour order 240): 2205,669.33 1565,669.33 1565,465.25 1435,465.25 1435,0 2205,0
NetC1_2 on Top Layer "TOP_LAYER_NETC1_2_P238" (solid, remove dead copper, pour order 238): 1818.22,385 1687.85,385 1564.74,508.11 1564.74,658.12 1573.78,667.17 1651.48,667.17 1659.74,658.91 1659.74,553.11 1691.55,521.3 1816.85,521.3 1824.74,513.41 1824.74,391.53
NetC10_2 on Top Layer "TOP_LAYER_NETC10_2_P233" (solid, remove dead copper, pour order 233): 883.91,620 955.61,620 955.61,570.13 883.91,570.13
NetC6_1 on Bottom Layer "BOTTOM_LAYER_NETC6_1_P244" (solid, remove dead copper, pour order 244): 2200,682.79 1435,682.79 1435,1400 2200,1400 2200,1020
NetC4_1 on Bottom Layer "Bottom Layer-No Net 2" (solid, pour order 245): 310,1020 818,1020 843.56,994.44 843.56,952.06 859.18,936.44 931.44,936.44 950,955 950,1195 813,1332 520,1332 301.37,1113.37 301.37,1028.63
NetC3_2 on Bottom Layer "Bottom Layer-No Net 1" (solid, pour order 243): 315,963.27 315,711.85 326.85,700 420,700 440,720 530,810 530,958.27 518.27,970 321.73,970
NetC2_1 on Bottom Layer "Bottom Layer-No Net" (solid, pour order 242): 1,710 280,710 285,715 285,785 285,865 280,870 0,870
SGND on Bottom Layer "Top Layer-No Net 1" (solid, pour order 246): 1435,670 1435,0 2200,0 2200,670
PGND on Bottom Layer "Top Layer-No Net" (solid, pour order 247): 0,1400 1380,1400 1380,0 0,0
SGND on Signal Layer 1 "Top Layer-No Net 1" (solid, pour order 254): 1435,1400 1435,0 2200,0 2200,1400
PGND on Signal Layer 1 "Top Layer-No Net" (solid, pour order 250): 0,1400 1060,1400 1380,1400 1380,898.33 1380,465 1380,0 0,0
SGND on Signal Layer 2 "Top Layer-No Net 1" (solid, pour order 252): 1435,1400 1435,0 2200,0 2200,1400
PGND on Signal Layer 2 "Top Layer-No Net" (solid, pour order 248): 0,1400 1060,1400 1380,1400 1380,898.33 1380,465 1380,0 0,0

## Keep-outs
Keep-Out Layer:
  the board outline again, w10
  text ".Layer_Name" at 487,-858.49 h60

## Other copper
Top Layer:
  pour cut-out: 1654.07,669.29 1654.07,790.51 1656.25,792.7 1695,792.7 1695,669.29
  pour cut-out: 1654.07,669.25 1653.98,669.33 1565,669.33 1565,699.76 1654.07,699.76
  pour cut-out: 1040.5,570 983.43,570 983.43,601.45 1040.18,601.45
  text ".Layer_Name" at 487,-858.49 h60
Signal Layer 1:
  text ".Layer_Name" at 487,-858.49 h60
Signal Layer 2:
  text ".Layer_Name" at 487,-858.49 h60
Bottom Layer:
  pour cut-out: 310.05,699.5 288.65,699.5 288.65,881.3 311.79,881.3
  pour cut-out: 301.16,1010 301.16,980 538.84,980 538.84,1010
  text ".Layer_Name" at 487,-858.49 h60

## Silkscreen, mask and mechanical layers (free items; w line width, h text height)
Top Overlay:
  lines w10: 1070,510 1070,546.15 1063,539.15 1076.13,539.15 1070,545.28 ; 1075.14,800 1070.14,805 1081.32,805 1076.32,800 1076.32,860.28 ; 1986.2,568.56 1986.2,568.8 2010,592.6 ; 2010,592.6 2010,585 2002.4,592.6 2010,592.6
  text "LM25184EVM-S12" at 574.29,1302 h60
  text "BSR110A" at 920.43,1208.89 h108.27
  text "EN" at 748,1194 h72.83
  text "VO+" at 2035,946.15 h50
  text "VIN+" at 62,901 h50
  text "SS/BIAS" at 383,900 h72.83
  text "VIN-" at 61,393 h50
  text "SW" at 916,339 h72.83
  text "GND" at 590,335 h72.83
  text "VO-" at 2030,320 h50
  text ".Layer_Name" at 487,-858.49 h60
Bottom Overlay:
  text ".Layer_Name" at 487,-858.49 h60
Top Paste:
  text ".Layer_Name" at 487,-858.49 h60
Bottom Paste:
  text ".Layer_Name" at 487,-858.49 h60
Top Solder:
  text ".Layer_Name" at 487,-858.49 h60
  text ".Layer_Name" at 487,-858.49 h60
Bottom Solder:
  text ".Layer_Name" at 487,-858.49 h60
Drill Guide:
  text ".Layer_Name" at 487,-858.49 h60
M1 Board Outline:
  the board outline again, w10
  text ".Layer_Name" at 487,-858.49 h60
M2 Board Dimensions:
  rectangle: 35,-400 410,-275
  rectangle: -90,-275 35,-150
  lines w7: -90,-275 910,-275 ; 35,-400 35,-150 ; 160,-400 160,-150 ; 410,-400 410,-150 ; 660,-400 660,-150 ; -90,-400 -90,-150 910,-150 910,-400 -90,-400
  text ".Layer_Name" at 487,-858.49 h60
M3 3D STEP Top:
  text ".Layer_Name" at 487,-858.49 h60
M4 3D STEP Bottom:
  text ".Layer_Name" at 487,-858.49 h60
M5 Assembly Top:
  lines w10: -382,-930.17 6218,-930.17 ; -382,-726.83 6220,-726.83 ; -382,-523.5 -382,-1133.5 3623,-1133.5 6220,-1133.5 6220,-523.5 -381.5,-523.5 -381.5,-1133.5 1194,-1133.5 ; 2083,-1133.5 2083,-523.5 ; 3350,-726.83 3350,-523.5 ; 4190,-726.83 4190,-523.5 ; 4812,-1140 4812,-937.17
  text "COMPONENTS MARKED 'DNP' SHOULD NOT BE POPULATED." at 1063.5,-318.5 h60
  text "ASSEMBLY VARIANT:" at 1063,-434 h60
  text ".VariantName" at 2099,-434 h60
  text "PCB VIEWED FROM TOP SIDE" at -318.5,-655.67 h60
  text "BOARD #:" at 2158,-655.67 h60
  text ".PRJ_Number" at 2703.5,-655.67 h60
  text "REV:" at 3548,-655.67 h60
  text ".PCB_Rev" at 3839.5,-655.67 h60
  text "SVN REV:" at 4386,-655.67 h60
  text ".VersionControl_RevNumber" at 4892,-655.67 h60
  text "TID #:" at 2158,-859 h60
  text ".TID" at 2703.5,-859 h60
  text "PLOT NAME =" at -318.5,-1064.34 h60
  text ".plot_File_Name" at 487,-1064.34 h60
  text "GENERATED    :" at 2160,-1064.34 h60
  text ".Print_Date" at 3029.5,-1064.34 h60
  text ".Print_Time" at 3758.5,-1064.34 h60
  text "TEXAS INSTRUMENTS" at 5023,-1064.34 h60
M6 Assembly Bottom:
  lines w10: -382.5,-727.33 6219.5,-727.33 ; -380.5,-930.67 6219.5,-930.67 ; 1025.5,-1140.5 1025.5,-937.67 ; 1647.5,-727.33 1647.5,-524 ; 2487.5,-727.33 2487.5,-524 ; 3754.5,-1134 3754.5,-524 ; 4643.5,-1134 6219,-1134 6219,-524 -382.5,-524 -382.5,-1134 2214.5,-1134 6219.5,-1134 6219.5,-524
  text "COMPONENTS MARKED 'DNP' SHOULD NOT BE POPULATED." at 6012,-318 h60
  text ".VariantName" at 4968,-434 h60
  text "ASSEMBLY VARIANT:" at 6007,-434 h60
  text ".VersionControl_RevNumber" at 945.5,-656.17 h60
  text "SVN REV:" at 1451.5,-656.17 h60
  text ".PCB_Rev" at 1998,-656.17 h60
  text "REV:" at 2289.5,-656.17 h60
  text ".PRJ_Number" at 3134,-656.17 h60
  text "BOARD #:" at 3679.5,-656.17 h60
  text "PCB VIEWED FROM BOTTOM SIDE" at 6156,-656.17 h60
  text ".TID" at 3134,-859.5 h60
  text "TID #:" at 3679.5,-859.5 h60
  text "TEXAS INSTRUMENTS" at 814.5,-1064.84 h60
  text ".Print_Time" at 2079,-1064.84 h60
  text ".Print_Date" at 2808,-1064.84 h60
  text "GENERATED    :" at 3677.5,-1064.84 h60
  text ".plot_File_Name" at 5350.5,-1064.84 h60
  text "PLOT NAME =" at 6156,-1064.84 h60
M9 Title Sheet:
  drawing of 57 lines, arcs and shapes, not listed
  text "1" at 649.84,8036.5 h70
  text "2" at 3145.5,8036.5 h70
  text "3" at 5634.84,8036.5 h70
  text "4" at 8141.51,8036.5 h70
  text "5" at 10640.5,8036.5 h70
  text "6" at 13145.5,8036.5 h70
  text "A" at -506.5,6893.5 h70
  text "A" at 14293.5,6893.5 h70
  text "B" at -506.5,4513.5 h70
  text "B" at 14293.5,4513.5 h70
  text "C" at -506.5,2138.5 h70
  text "C" at 14293.5,2138.5 h70
  text "PROJECT TITLE:" at 11253.5,277.5 h45
  text ".PRJ_Title" at 11303.5,144.17 h70
  text "DESIGNED FOR:" at 11253.5,-23.5 h45
  text ".PRJ_Customer" at 11303.5,-163.5 h70
  text "D" at -506.5,-231.5 h70
  text "D" at 14293.5,-231.5 h70
  text "FILE NAME:" at 11253.5,-323.5 h45
  text ".PCB_File_Name_No_Path" at 11303.5,-443.5 h70
  text "Texas Instruments (TI) and/or its licensors do not warrant the accuracy or completeness of this specification" at 6284,-605.34 h45
  text "ENGINEER:" at 11253.5,-613.5 h45
  text "LAYOUT BY:" at 12758.5,-613.5 h45
  text "or any information contained therein. TI and/or its licensors do not warrant that this design will meet" at 6239.01,-718 h45
  text ".PRJ_Engineer" at 11303.5,-768.49 h70
  text ".PCB_Layout" at 12809,-768.49 h70
  text "the specifications, will be suitable for your application or fit for any particular purpose, or will operate in" at 6239.01,-830.67 h45
  text ".Layer_Name" at 487,-858.49 h60
  text "ALTIUM DESIGNER VERSION:" at 12758.5,-923.5 h45
  text "an implementation. TI and/or its licensors do not warrant that the design is production worthy. You should" at 6239.01,-943.33 h45
  text "completely validate and test your design implementation to confirm the system functionality for your application." at 6284,-1056 h45
  text ".print_Scale" at 11303.5,-1056.83 h70
  text ".Application_BuildNumber" at 12809,-1056.83 h70
  text "1" at 649.84,-1263.5 h70
  text "2" at 3145.5,-1263.5 h70
  text "3" at 5634.84,-1263.5 h70
  text "4" at 8141.51,-1263.5 h70
  text "5" at 10640.5,-1263.5 h70
  text "6" at 13145.5,-1263.5 h70
M10 Fab Notes:
  drawing of 189 lines, arcs and shapes, not listed
  text "DESIGN INFORMATION" at 12292.02,6356.17 h60
  text "MIN. TRACK WIDTH:" at 11647.46,6224.05 h60
  text "8" at 12743.7,6224.05 h60
  text "MIL" at 12898.46,6224.05 h60
  text "MIN. CLEARANCE:" at 11647.46,6099.92 h60
  text "0.2" at 12683.7,6099.93 h60
  text "mm" at 12898.46,6099.92 h60
  text "MIN. VIA PAD SIZE:" at 11647.46,5975.8 h60
  text "24" at 12713.71,5975.8 h60
  text "MIL" at 12898.46,5975.8 h60
  text "0.05mm (2MIL)" at 12342.46,5845.9 h60
  text "MINIMUM ANNULAR RING" at 11318.23,5837.67 h60
  text "EXTERNAL" at 13050.46,5837.67 h60
  text "PER" at 11518.23,5727.55 h60
  text "IPC-D-275 CLASS 2 LEVEL C" at 11738.23,5727.54 h60
  text "MIL, HOLES" at 13226.46,5627.07 h60
  text "+/-" at 12834,5618.48 h60
  text "+/-" at 13688,5618.48 h60
  text "REGISTRATION TOLERANCES:" at 11318.23,5617.42 h60
  text "METAL" at 12518,5617.42 h60
  text "5" at 13094.2,5617.42 h60
  text "3" at 13927.2,5617.42 h60
  text "MIL" at 14043.46,5617.42 h60
  text "HOLE SIZE TOLERANCE (UNLESS OTHERWISE SPECIFIED):" at 11318.23,5519.1 h60
  text "+/-" at 13688,5516.23 h60
  text "3" at 13927.2,5515.17 h60
  text "MIL" at 14043.46,5515.17 h60
  text "MATERIAL:" at 11243.46,5377.52 h60
  text "FR-4 High Tg" at 12229.9,5249 h60
  text "X" at 12085.46,5241.01 h60
  text "FR-408" at 11664.46,5236.49 h60
  text "OTHER" at 13152.46,5236.49 h60
  text "62 MIL (1.6mm) +/-10%" at 11984.56,5093.46 h60
  text "X" at 11864.46,5091.01 h60
  text "THICKNESS:" at 11318.23,5085.24 h60
  text "OTHER" at 13269.46,5085.24 h60
  text "TOLERANCE:" at 11318.23,4946.92 h60
  text "X" at 12166.46,4946.92 h60
  text "ANSI IPC-6012 TYPE 3 CLASS 2" at 12344.48,4946.92 h60
  text "OTHER +/-" at 12344.46,4802.73 h60
  text "BOW & TWIST:" at 11318.23,4657.54 h60
  text "X" at 12166.46,4657.54 h60
  text "ANSI IPC-6012 TYPE 3 CLASS 2" at 12344.48,4657.54 h60
  text "OTHER +/-" at 12344.46,4510.85 h60
  text "DRILLING:" at 11243.46,4380.23 h60
  text "NC_DRILL FILES" at 13004.46,4275.04 h60
  text "REFERENCE:" at 11318.23,4271.1 h60
  text "X" at 11975.46,4271.01 h60
  text "AS SHOWN" at 12153.46,4271.1 h60
  text "X" at 12876.46,4271.1 h60
  text "OTHER" at 13302.46,4128.85 h60
  text "PTH COPPER THICKNESS:" at 11317.91,4125.32 h60
  text "X" at 12457.14,4125.32 h60
  text "20-30 um" at 12585.14,4125.32 h60
  text "BOARD FINISH:" at 11243.46,3977.73 h60
  text "SILKSCREEN:" at 11398.68,3867.6 h60
  text "X" at 12356.46,3867.6 h60
  text "TOP" at 12473.46,3867.6 h60
  text "X" at 12866.46,3867.6 h60
  text "BOTTOM" at 12984.46,3867.6 h60
  text "SILKSCREEN COLOR:" at 11398.68,3712.41 h60
  text "X" at 12355.46,3712.41 h60
  text "WHITE" at 12473.46,3712.41 h60
  text "OTHER" at 12984.46,3712.41 h60
  text "X" at 12486.46,3568.96 h60
  text "GREEN" at 12604.46,3568.96 h60
  text "OTHER" at 13222.46,3568.96 h60
  text "SOLDER RESIST COLOR:" at 11398.68,3562.1 h60
  text "X" at 12486.46,3414.71 h60
  text "MATTE" at 12604.46,3414.71 h60
  text "SEMI-GLOSS" at 13222,3414.07 h60
  text "IMMERSION GOLD (ENIG)" at 12304.46,3241.94 h60
  text "ENEPIG" at 13642,3234.72 h60
  text "SURFACE FINISH:" at 11243.46,3233.72 h60
  text "X" at 12126.46,3233.72 h60
  text "IMM. TIN/SILVER OR EQUIV" at 11573,3096.4 h60
  text "OTHER" at 13004.46,3092.47 h60
  text "ARRAY/PANEL:" at 11243.46,2937.09 h60
  text "CUT AND TRIM PER M1 BOARD OUTLINE" at 12304.46,2928.87 h60
  text "N.C. ROUTE" at 12304.46,2792.9 h60
  text "X" at 12992.46,2792.9 h60
  text "V. SCORE" at 13170.46,2792.9 h60
  text "CERTIFICATION:" at 11243.46,2663.77 h60
  text "MATERIALS AND WORKMANSHIP FOR ALL PCBS" at 11968.46,2663.77 h60
  text "TO MEET OR EXCEED THE REQUIREMENTS OF:" at 11968.46,2569.71 h60
  text "X" at 11605.97,2441.08 h60
  text "ANSI IPC-A-600F CLASS ->" at 11733.96,2441.08 h60
  text "X" at 13381.97,2441.08 h60
  text "2" at 13491.96,2441.08 h60
  text "1" at 13176.96,2439.58 h60
  text "3" at 13845.96,2439.58 h60
  text "X" at 12417.97,2293.39 h60
  text "RoHS" at 12545.96,2293.39 h60
  text "OTHER" at 13190.36,2293.39 h60
  text "PER ORDER" at 13587.42,2293.39 h60
  text "ALL BOARDS MUST MEET OR EXCEED UL94-V0 REQUIREMENTS." at 11271,2139.57 h60
  text "PCB MUST BEAR THE UL94V-0 UL REGISTERED MATERIAL ID NUMBER" at 11271,2023.5 h60
  text "ADDITIONAL REQUIREMENTS:" at 11243.46,1854.08 h60
  text "MICROSECTION:" at 11318.23,1746.95 h60
  text "YES" at 12223.96,1746.95 h60
  text "REQUIRED" at 13085.46,1602.62 h60
  text "BARE BOARD ELEC. TEST:" at 11318.23,1599.76 h60
  text "NONE" at 12623.96,1599.76 h60
  text "X" at 12967.46,1599.76 h60
  text "PER ORDER" at 13677.46,1599.76 h60
  text "XX MIL VIAS REQUIRE NON-CONDUCTIVE FILL AND PLANARIZE" at 11486.38,1394.82 h59
  text "XX MIL VIAS REQUIRE CONDUCTIVE FILL AND PLANARIZE" at 11494.38,1290.84 h60
  text "OUTER XX MIL VIAS REQUIRE 50 OHM SINGLE-ENDED IMPEDANCE" at 11493.39,1127.46 h58
  text "LAYER 2 & 3 (INNER LAYERS) XX MIL WIDE, XX MIL SPACE / TRACES REQUIRE 100 OHM DIFFERENTIAL IMPEDANCE" at 11485.39,891.74 h60
  text ".Layer_Name" at 487,-858.49 h60
M11 Gerber Information:
  lines w10: -382,-930.17 6218,-930.17 ; -382,-726.83 6220,-726.83 ; -382,-523.5 -382,-1133.5 3623,-1133.5 6220,-1133.5 6220,-523.5 -381.5,-523.5 -381.5,-1133.5 1194,-1133.5 ; 2083,-1133.5 2083,-523.5 ; 3350,-726.83 3350,-523.5 ; 4190,-726.83 4190,-523.5 ; 4812,-1140 4812,-937.17
  text "ALL ARTWORK VIEWED FROM TOP SIDE" at -318.5,-655.67 h60
  text "BOARD #:" at 2158,-655.67 h60
  text ".PRJ_Number" at 2703.5,-655.67 h60
  text "REV:" at 3548,-655.67 h60
  text ".PCB_Rev" at 3839.5,-655.67 h60
  text "SVN REV:" at 4386,-655.67 h60
  text ".VersionControl_RevNumber" at 4892,-655.67 h60
  text "LAYER NAME =" at -318.5,-858.49 h60
  text "TID #:" at 2158,-859 h60
  text ".TID" at 2703.5,-859 h60
  text "PLOT NAME =" at -318.5,-1064.34 h60
  text ".plot_File_Name" at 487,-1064.34 h60
  text "GENERATED    :" at 2160,-1064.34 h60
  text ".Print_Date" at 3029.5,-1064.34 h60
  text ".Print_Time" at 3758.5,-1064.34 h60
  text "TEXAS INSTRUMENTS" at 5023,-1064.34 h60
M12 Stackup:
  drawing of 295 lines, arcs and shapes, not listed
  text "Layer" at 9720.35,7775 h60
  text "Name" at 10130.26,7775 h60
  text "Material" at 11070,7775 h60
  text "Thickness" at 11929.77,7775 h60
  text "Constant" at 12579.6,7775 h60
  text "Board Layer Stack" at 13149.46,7775 h60
  text "Top Overlay" at 10130.26,7655 h60
  text "Top Solder" at 10130.26,7535 h60
  text "Solder Resist" at 11070,7535 h60
  text "0.40mil" at 11929.77,7535 h60
  text "3.5" at 12579.6,7535 h60
  text "1" at 9720.35,7415 h60
  text "Top Layer" at 10130.26,7415 h60
  text "Copper" at 11070,7415 h60
  text "1.42mil" at 11929.77,7415 h60
  text "Dielectric1" at 10130.26,7295 h60
  text "FR-4 High Tg" at 11070,7295 h60
  text "6.00mil" at 11929.77,7295 h60
  text "4.2" at 12579.6,7295 h60
  text "2" at 9720.35,7175 h60
  text "Signal Layer 1" at 10130.26,7175 h60
  text "Copper" at 11070,7175 h60
  text "1.42mil" at 11929.77,7175 h60
  text "Dielectric 2" at 10130.26,7055 h60
  text "FR-4 High Tg" at 11070,7055 h60
  text "44.00mil" at 11929.77,7055 h60
  text "4.2" at 12579.6,7055 h60
  text "3" at 9720.35,6935 h60
  text "Signal Layer 2" at 10130.26,6935 h60
  text "Copper" at 11070,6935 h60
  text "1.42mil" at 11929.77,6935 h60
  text "Dielectric 3" at 10130.26,6815 h60
  text "FR-4 High Tg" at 11070,6815 h60
  text "6.00mil" at 11929.77,6815 h60
  text "4.2" at 12579.6,6815 h60
  text "4" at 9720.35,6695 h60
  text "Bottom Layer" at 10130.26,6695 h60
  text "Copper" at 11070,6695 h60
  text "1.42mil" at 11929.77,6695 h60
  text "Bottom Solder" at 10130.26,6575 h60
  text "Solder Resist" at 11070,6575 h60
  text "0.40mil" at 11929.77,6575 h60
  text "3.5" at 12579.6,6575 h60
  text "Bottom Overlay" at 10130.26,6455 h60
  text ".Layer_Name" at 487,-858.49 h60
M13 Component Bodies Top:
  text ".Layer_Name" at 487,-858.49 h60
M14 Component Bodies Bottom:
  text ".Layer_Name" at 487,-858.49 h60
M15 Courtyards Top:
  text ".Layer_Name" at 487,-858.49 h60
M16 Courtyards Bottom:
  text ".Layer_Name" at 487,-858.49 h60
Drill Drawing:
  lines w10: 5246.09,2973.7 5301.34,2973.7 5301.34,3028.95 5246.09,3028.95 5246.09,2973.7 ; 5246.09,3153.27 5301.34,3153.27 5273.72,3098.02 5246.09,3153.27 ; 5246.09,3236.15 5259.9,3236.15 5259.9,3222.34 5287.53,3222.34 5287.53,3236.15 5301.34,3236.15 5301.34,3263.78 5287.53,3263.78 5287.53,3277.59 5259.9,3277.59 5259.9,3263.78 5246.09,3263.78 5246.09,3236.15 ; 5246.09,3360.47 5259.9,3360.47 5273.72,3346.66 5287.53,3360.47 5301.34,3360.47 5287.53,3374.28 5301.34,3388.1 5287.53,3388.1 5273.72,3401.91 5259.9,3388.1 5246.09,3388.1 5259.9,3374.28 5246.09,3360.47
  lines w12: 5196,2936.4 8427.49,2936.4 ; 5196,3433.68 8427.49,3433.68 ; 5533.86,2812.08 5533.86,3558 ; 5865.86,2812.08 5865.86,3558 ; 6502.43,2812.08 6502.43,3558 ; 6761.57,2812.08 6761.57,3558 ; 7136.72,2812.08 7136.72,3558 ; 7861.05,2812.08 7861.05,3558 ; 5196,2812.08 8427.49,2812.08 8427.49,3558 5196,3558 5196,2812.08
  text "Symbol" at 5270.59,3470.98 h72
  text "Quantity" at 5571.16,3470.98 h72
  text "Finished Hole Size" at 5903.16,3470.98 h72
  text "Plated" at 6539.72,3470.98 h72
  text "Hole Type" at 6798.86,3470.98 h72
  text "Drill Layer Pair" at 7174.02,3470.98 h72
  text "Hole Tolerance" at 7898.35,3470.98 h72
  text "4" at 5571.16,3346.66 h60
  text "7.87mil (0.200mm)" at 5903.16,3346.66 h60
  text "PTH" at 6539.72,3346.66 h60
  text "Round" at 6798.86,3346.66 h60
  text "Top Layer - Bottom Layer" at 7174.02,3346.66 h60
  text "32" at 5571.16,3222.34 h60
  text "10.00mil (0.254mm)" at 5903.16,3222.34 h60
  text "PTH" at 6539.72,3222.34 h60
  text "Round" at 6798.86,3222.34 h60
  text "Top Layer - Bottom Layer" at 7174.02,3222.34 h60
  text "4" at 5571.16,3098.02 h60
  text "80.71mil (2.050mm)" at 5903.16,3098.02 h60
  text "PTH" at 6539.72,3098.02 h60
  text "Round" at 6798.86,3098.02 h60
  text "Top Layer - Bottom Layer" at 7174.02,3098.02 h60
  text "4" at 5571.16,2973.7 h60
  text "125.00mil (3.175mm)" at 5903.16,2973.7 h60
  text "PTH" at 6539.72,2973.7 h60
  text "Round" at 6798.86,2973.7 h60
  text "Top Layer - Bottom Layer" at 7174.02,2973.7 h60
  text "44 Total" at 5571.16,2849.38 h60
  text ".Layer_Name" at 487,-858.49 h60
M17 Embedded Cavity:
  text ".Layer_Name" at 487,-858.49 h60
M18 Embedded Assembly:
  text ".Layer_Name" at 487,-858.49 h60
M19 Embedded Keepout:
  text ".Layer_Name" at 487,-858.49 h60

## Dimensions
-90,-400 to 910,-400 on M2 Board Dimensions
0,0 to 2200,0 on M2 Board Dimensions
0,0 to 0,1400 on M2 Board Dimensions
